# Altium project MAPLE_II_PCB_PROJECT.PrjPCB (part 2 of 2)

## Sheet MAPLE_II_HIGH_DENSITY_EXPANSION.SchDoc: High Density Expansion
size B; CompanyName: LeafLabs; DrawnBy: David McCoy; Engineer: David McCoy; Organization: LeafLabs; DocumentNumber: 6; Revision: A; SheetNumber: 6; SheetTotal: 6; ProjectPrettyName: Maple II
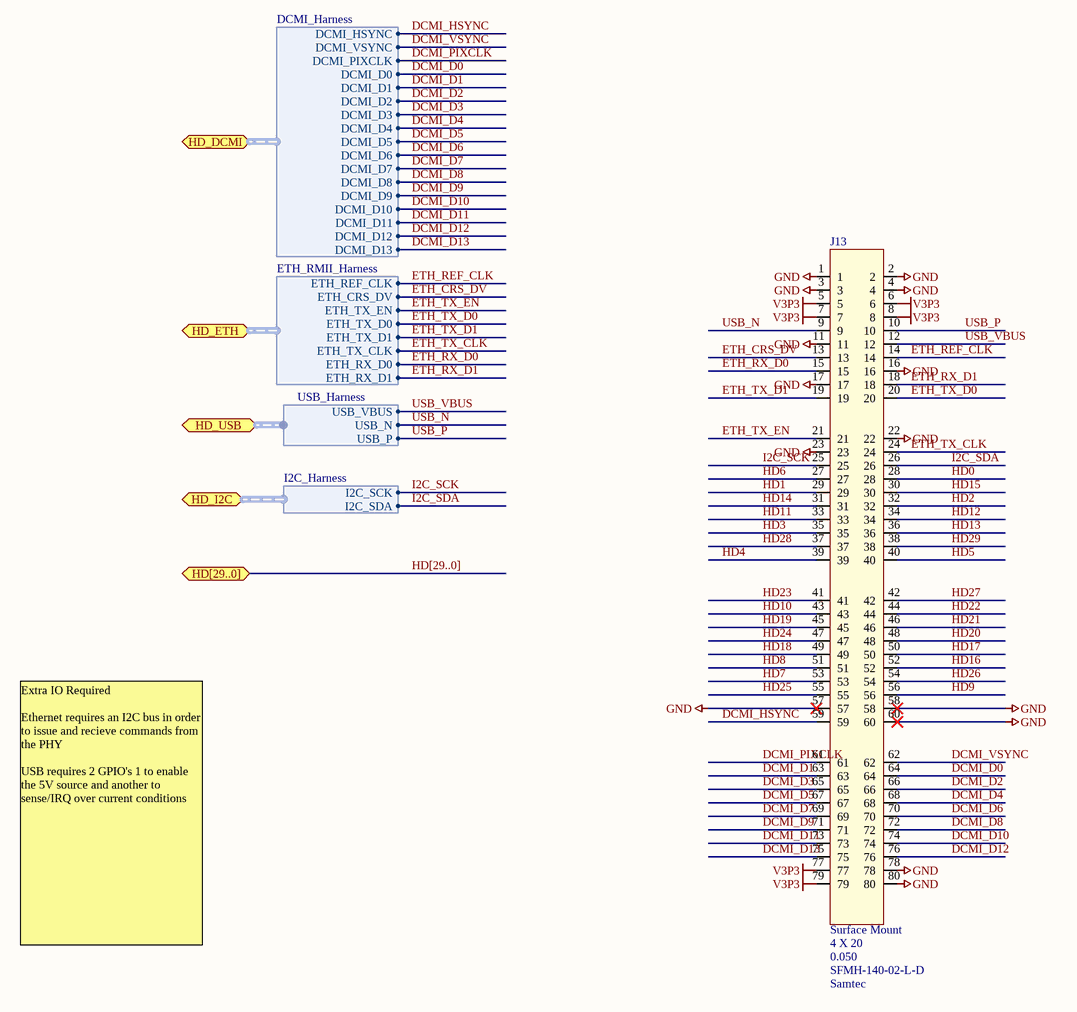
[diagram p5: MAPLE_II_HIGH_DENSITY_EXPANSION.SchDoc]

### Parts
J13  Mounting Type: Surface Mount  Number of Positions: 4 X 20  Pitch: 0.050  Manufacturer Part Number: SFMH-140-02-L-D  Manufacturer: Samtec  [SFMH-140]  (hidden comment: J_SFMH-140-02-L-D)

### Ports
HD[29..0], HD_DCMI (harness DCMI_Harness), HD_ETH (harness ETH_RMII_Harness), HD_I2C (harness I2C_Harness), HD_USB (harness USB_Harness)

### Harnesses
DCMI_Harness: DCMI_HSYNC, DCMI_VSYNC, DCMI_PIXCLK, DCMI_D0, DCMI_D1, DCMI_D2, DCMI_D3, DCMI_D4, DCMI_D5, DCMI_D6, DCMI_D7, DCMI_D8, DCMI_D9, DCMI_D10, DCMI_D11, DCMI_D12, DCMI_D13
ETH_RMII_Harness: ETH_REF_CLK, ETH_CRS_DV, ETH_TX_EN, ETH_TX_D0, ETH_TX_D1, ETH_TX_CLK, ETH_RX_D0, ETH_RX_D1
I2C_Harness: I2C_SCK, I2C_SDA
USB_Harness: USB_VBUS, USB_N, USB_P

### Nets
GND: J13.1 J13.2 J13.3 J13.4 J13.11 J13.16 J13.17 J13.22 J13.23 J13.57 J13.58 J13.60 J13.78 J13.80
V3P3: J13.5 J13.6 J13.7 J13.8 J13.77 J13.79
DCMI_D0: J13.64 ; port HD_DCMI.DCMI_D0
DCMI_D1: J13.63 ; port HD_DCMI.DCMI_D1
DCMI_D2: J13.66 ; port HD_DCMI.DCMI_D2
DCMI_D3: J13.65 ; port HD_DCMI.DCMI_D3
DCMI_D4: J13.68 ; port HD_DCMI.DCMI_D4
DCMI_D5: J13.67 ; port HD_DCMI.DCMI_D5
DCMI_D6: J13.70 ; port HD_DCMI.DCMI_D6
DCMI_D7: J13.69 ; port HD_DCMI.DCMI_D7
DCMI_D8: J13.72 ; port HD_DCMI.DCMI_D8
DCMI_D9: J13.71 ; port HD_DCMI.DCMI_D9
DCMI_D10: J13.74 ; port HD_DCMI.DCMI_D10
DCMI_D11: J13.73 ; port HD_DCMI.DCMI_D11
DCMI_D12: J13.76 ; port HD_DCMI.DCMI_D12
DCMI_D13: J13.75 ; port HD_DCMI.DCMI_D13
DCMI_HSYNC: J13.59 ; port HD_DCMI.DCMI_HSYNC
DCMI_PIXCLK: J13.61 ; port HD_DCMI.DCMI_PIXCLK  [project net D13]
DCMI_VSYNC: J13.62 ; port HD_DCMI.DCMI_VSYNC
ETH_CRS_DV: J13.13 ; port HD_ETH.ETH_CRS_DV  [project net D11]
ETH_REF_CLK: J13.14 ; port HD_ETH.ETH_REF_CLK  [project net D3]
ETH_RX_D0: J13.15 ; port HD_ETH.ETH_RX_D0
ETH_RX_D1: J13.18 ; port HD_ETH.ETH_RX_D1
ETH_TX_CLK: J13.24 ; port HD_ETH.ETH_TX_CLK
ETH_TX_D0: J13.20 ; port HD_ETH.ETH_TX_D0
ETH_TX_D1: J13.19 ; port HD_ETH.ETH_TX_D1
ETH_TX_EN: J13.21 ; port HD_ETH.ETH_TX_EN
HD0: J13.28
HD1: J13.29
HD2: J13.32
HD3: J13.35
HD4: J13.39
HD5: J13.40
HD6: J13.27
HD7: J13.53
HD8: J13.51
HD9: J13.56
HD10: J13.43
HD11: J13.33
HD12: J13.34
HD13: J13.36
HD14: J13.31
HD15: J13.30
HD16: J13.52
HD17: J13.50
HD18: J13.49
HD19: J13.45
HD20: J13.48
HD21: J13.46
HD22: J13.44
HD23: J13.41
HD24: J13.47
HD25: J13.55
HD26: J13.54
HD27: J13.42
HD28: J13.37
HD29: J13.38
I2C_SCK: J13.25 ; port HD_I2C.I2C_SCK  [project net D16]
I2C_SDA: J13.26 ; port HD_I2C.I2C_SDA  [project net D15]
USB_N: J13.9 ; port HD_USB.USB_N
USB_P: J13.10 ; port HD_USB.USB_P
USB_VBUS: J13.12 ; port HD_USB.USB_VBUS

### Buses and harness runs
bus HD[29..0] = port HD[29..0]

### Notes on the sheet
- Extra IO Required
  Ethernet requires an I2C bus in order to issue and recieve commands from the PHY
  USB requires 2 GPIO's 1 to enable the 5V source and another to sense/IRQ over current conditions

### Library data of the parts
J13 = J_SFMH-140-02-L-D: CONN RECEPT 4ROW X 20POS .50" SMT

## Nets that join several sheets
GND: MAPLE_II_PROCESSOR (76 pins), MAPLE_II_COMM_PROCESSOR (59 pins), MAPLE_II_POWER (19 pins), MAPLE_II_EXPANSION (7 pins), MAPLE_II_HIGH_DENSITY_EXPANSION (14 pins)
V3P3: MAPLE_II_PROCESSOR (41 pins), MAPLE_II_COMM_PROCESSOR (19 pins), MAPLE_II_POWER (6 pins), MAPLE_II_EXPANSION (J2.5 R1.1 R3.1), MAPLE_II_HIGH_DENSITY_EXPANSION (6 pins)
V5P0: MAPLE_II_POWER (C2.2 J7.2 U1.21), MAPLE_II_EXPANSION (J2.7)
V_USB_5P0: MAPLE_II_COMM_PROCESSOR (J1.1), MAPLE_II_POWER (J7.3)
VA3P3: MAPLE_II_PROCESSOR (C29.2 C30.2 L3.1 U2.R1), MAPLE_II_EXPANSION (J2.4)
VIN: MAPLE_II_POWER (J6.2 J7.1), MAPLE_II_EXPANSION (J2.1)
A0: MAPLE_II_PROCESSOR (U2.E2), MAPLE_II_EXPANSION (J4.1)
A1: MAPLE_II_PROCESSOR (U2.H3), MAPLE_II_EXPANSION (J4.2)
A2: MAPLE_II_PROCESSOR (U2.H2), MAPLE_II_EXPANSION (J4.3)
A3: MAPLE_II_PROCESSOR (U2.J2), MAPLE_II_EXPANSION (J4.4)
A4: MAPLE_II_PROCESSOR (U2.J3), MAPLE_II_EXPANSION (J4.5)
A5: MAPLE_II_PROCESSOR (U2.K3), MAPLE_II_EXPANSION (J4.6)
BOOT0: MAPLE_II_PROCESSOR (U2.D6 U2.D10), MAPLE_II_COMM_PROCESSOR (U3.35), MAPLE_II_EXPANSION (C1.2 R1.2 S1.1)
BOOT1: MAPLE_II_PROCESSOR (J10.1 R19.1 U2.M6), MAPLE_II_COMM_PROCESSOR (U3.14)
COMM_UART1_RX: MAPLE_II_PROCESSOR (U2.R12), MAPLE_II_COMM_PROCESSOR (U3.26)
COMM_UART1_TX: MAPLE_II_PROCESSOR (U2.R13), MAPLE_II_COMM_PROCESSOR (U3.25)
D0: MAPLE_II_PROCESSOR (U2.R2), MAPLE_II_EXPANSION (J5.1)
D1: MAPLE_II_PROCESSOR (U2.P2), MAPLE_II_EXPANSION (J5.2)
D2: MAPLE_II_PROCESSOR (U2.N3), MAPLE_II_EXPANSION (J5.3)
D3: MAPLE_II_PROCESSOR (U2.N2), MAPLE_II_EXPANSION (J5.4), MAPLE_II_HIGH_DENSITY_EXPANSION (J13.14)
D4: MAPLE_II_PROCESSOR (R34#1.2 U2.A6), MAPLE_II_EXPANSION (J5.5)
D5: MAPLE_II_PROCESSOR (U2.B6), MAPLE_II_EXPANSION (J5.6)
D6: MAPLE_II_PROCESSOR (U2.F15), MAPLE_II_EXPANSION (J5.7)
D7: MAPLE_II_PROCESSOR (U2.E15), MAPLE_II_EXPANSION (J5.8)
D8: MAPLE_II_PROCESSOR (R15.2 U2.D15), MAPLE_II_EXPANSION (J3.1)
D9: MAPLE_II_PROCESSOR (U2.B5), MAPLE_II_EXPANSION (J3.2)
D10: MAPLE_II_PROCESSOR (U2.N4), MAPLE_II_EXPANSION (J3.3)
D11: MAPLE_II_PROCESSOR (U2.R3), MAPLE_II_EXPANSION (J3.4), MAPLE_II_HIGH_DENSITY_EXPANSION (J13.13)
D12: MAPLE_II_PROCESSOR (U2.P3), MAPLE_II_EXPANSION (J3.5)
D13: MAPLE_II_PROCESSOR (U2.P4), MAPLE_II_EXPANSION (J3.6 LED1.2), MAPLE_II_HIGH_DENSITY_EXPANSION (J13.61)
D14: MAPLE_II_PROCESSOR (U2.F14), MAPLE_II_EXPANSION (J3.8)
D15: MAPLE_II_PROCESSOR (U2.J4), MAPLE_II_EXPANSION (J3.9), MAPLE_II_HIGH_DENSITY_EXPANSION (J13.26)
D16: MAPLE_II_PROCESSOR (U2.H4), MAPLE_II_EXPANSION (J3.10), MAPLE_II_HIGH_DENSITY_EXPANSION (J13.25)
DCMI_D0: MAPLE_II_PROCESSOR (U2.H15), MAPLE_II_HIGH_DENSITY_EXPANSION (J13.64)
DCMI_D1: MAPLE_II_PROCESSOR (U2.G15), MAPLE_II_HIGH_DENSITY_EXPANSION (J13.63)
DCMI_D2: MAPLE_II_PROCESSOR (U2.G14), MAPLE_II_HIGH_DENSITY_EXPANSION (J13.66)
DCMI_D3: MAPLE_II_PROCESSOR (U2.A3), MAPLE_II_HIGH_DENSITY_EXPANSION (J13.65)
DCMI_D4: MAPLE_II_PROCESSOR (R35#1.2 U2.B13), MAPLE_II_HIGH_DENSITY_EXPANSION (J13.68)
DCMI_D5: MAPLE_II_PROCESSOR (U2.D4), MAPLE_II_HIGH_DENSITY_EXPANSION (J13.67)
DCMI_D6: MAPLE_II_PROCESSOR (U2.A5), MAPLE_II_HIGH_DENSITY_EXPANSION (J13.70)
DCMI_D7: MAPLE_II_PROCESSOR (U2.B4), MAPLE_II_HIGH_DENSITY_EXPANSION (J13.69)
DCMI_D8: MAPLE_II_PROCESSOR (U2.B14), MAPLE_II_HIGH_DENSITY_EXPANSION (J13.72)
DCMI_D9: MAPLE_II_PROCESSOR (U2.A12), MAPLE_II_HIGH_DENSITY_EXPANSION (J13.71)
DCMI_D10: MAPLE_II_PROCESSOR (U2.C13), MAPLE_II_HIGH_DENSITY_EXPANSION (J13.74)
DCMI_D11: MAPLE_II_PROCESSOR (U2.D12), MAPLE_II_HIGH_DENSITY_EXPANSION (J13.73)
DCMI_D12: MAPLE_II_PROCESSOR (U2.P6), MAPLE_II_HIGH_DENSITY_EXPANSION (J13.76)
DCMI_D13: MAPLE_II_PROCESSOR (U2.B7), MAPLE_II_HIGH_DENSITY_EXPANSION (J13.75)
DCMI_HSYNC: MAPLE_II_PROCESSOR (U2.M12), MAPLE_II_HIGH_DENSITY_EXPANSION (J13.59)
DCMI_VSYNC: MAPLE_II_PROCESSOR (U2.C4), MAPLE_II_HIGH_DENSITY_EXPANSION (J13.62)
ETH_RX_D0: MAPLE_II_PROCESSOR (U2.N5), MAPLE_II_HIGH_DENSITY_EXPANSION (J13.15)
ETH_RX_D1: MAPLE_II_PROCESSOR (U2.P5), MAPLE_II_HIGH_DENSITY_EXPANSION (J13.18)
ETH_TX_CLK: MAPLE_II_PROCESSOR (U2.D1), MAPLE_II_HIGH_DENSITY_EXPANSION (J13.24)
ETH_TX_D0: MAPLE_II_PROCESSOR (U2.A8), MAPLE_II_HIGH_DENSITY_EXPANSION (J13.20)
ETH_TX_D1: MAPLE_II_PROCESSOR (U2.A7), MAPLE_II_HIGH_DENSITY_EXPANSION (J13.19)
ETH_TX_EN: MAPLE_II_PROCESSOR (U2.B9), MAPLE_II_HIGH_DENSITY_EXPANSION (J13.21)
HD0: MAPLE_II_PROCESSOR (U2.M2), MAPLE_II_HIGH_DENSITY_EXPANSION (J13.28)
HD1: MAPLE_II_PROCESSOR (U2.M3), MAPLE_II_HIGH_DENSITY_EXPANSION (J13.29)
HD2: MAPLE_II_PROCESSOR (U2.M4), MAPLE_II_HIGH_DENSITY_EXPANSION (J13.32)
HD3: MAPLE_II_PROCESSOR (U2.M5), MAPLE_II_HIGH_DENSITY_EXPANSION (J13.35)
HD4: MAPLE_II_PROCESSOR (U2.E1), MAPLE_II_HIGH_DENSITY_EXPANSION (J13.39)
HD5: MAPLE_II_PROCESSOR (U2.F1), MAPLE_II_HIGH_DENSITY_EXPANSION (J13.40)
HD6: MAPLE_II_PROCESSOR (U2.P12), MAPLE_II_HIGH_DENSITY_EXPANSION (J13.27)
HD7: MAPLE_II_PROCESSOR (R28.2 U2.C15), MAPLE_II_HIGH_DENSITY_EXPANSION (J13.53)
HD8: MAPLE_II_PROCESSOR (R31#1.2 U2.B15), MAPLE_II_HIGH_DENSITY_EXPANSION (J13.51)
HD9: MAPLE_II_PROCESSOR (U2.B12), MAPLE_II_HIGH_DENSITY_EXPANSION (J13.56)
HD10: MAPLE_II_PROCESSOR (U2.C12), MAPLE_II_HIGH_DENSITY_EXPANSION (J13.43)
HD11: MAPLE_II_PROCESSOR (U2.P10), MAPLE_II_HIGH_DENSITY_EXPANSION (J13.33)
HD12: MAPLE_II_PROCESSOR (U2.R10), MAPLE_II_HIGH_DENSITY_EXPANSION (J13.34)
HD13: MAPLE_II_PROCESSOR (U2.N11), MAPLE_II_HIGH_DENSITY_EXPANSION (J13.36)
HD14: MAPLE_II_PROCESSOR (U2.P11), MAPLE_II_HIGH_DENSITY_EXPANSION (J13.31)
HD15: MAPLE_II_PROCESSOR (U2.R11), MAPLE_II_HIGH_DENSITY_EXPANSION (J13.30)
HD16: MAPLE_II_PROCESSOR (U2.L13), MAPLE_II_HIGH_DENSITY_EXPANSION (J13.52)
HD17: MAPLE_II_PROCESSOR (U2.L12), MAPLE_II_HIGH_DENSITY_EXPANSION (J13.50)
HD18: MAPLE_II_PROCESSOR (U2.K12), MAPLE_II_HIGH_DENSITY_EXPANSION (J13.49)
HD19: MAPLE_II_PROCESSOR (U2.E12), MAPLE_II_HIGH_DENSITY_EXPANSION (J13.45)
HD20: MAPLE_II_PROCESSOR (U2.E13), MAPLE_II_HIGH_DENSITY_EXPANSION (J13.48)
HD21: MAPLE_II_PROCESSOR (U2.D13), MAPLE_II_HIGH_DENSITY_EXPANSION (J13.46)
HD22: MAPLE_II_PROCESSOR (U2.C3), MAPLE_II_HIGH_DENSITY_EXPANSION (J13.44)
HD23: MAPLE_II_PROCESSOR (U2.C2), MAPLE_II_HIGH_DENSITY_EXPANSION (J13.41)
HD24: MAPLE_II_PROCESSOR (U2.E14), MAPLE_II_HIGH_DENSITY_EXPANSION (J13.47)
HD25: MAPLE_II_PROCESSOR (U2.D14), MAPLE_II_HIGH_DENSITY_EXPANSION (J13.55)
HD26: MAPLE_II_PROCESSOR (U2.C14), MAPLE_II_HIGH_DENSITY_EXPANSION (J13.54)
HD27: MAPLE_II_PROCESSOR (U2.D3), MAPLE_II_HIGH_DENSITY_EXPANSION (J13.42)
HD28: MAPLE_II_PROCESSOR (U2.E3), MAPLE_II_HIGH_DENSITY_EXPANSION (J13.37)
HD29: MAPLE_II_PROCESSOR (U2.E4), MAPLE_II_HIGH_DENSITY_EXPANSION (J13.38)
~{MCU_RST}: MAPLE_II_PROCESSOR (R22.1 S2.1 U2.J1), MAPLE_II_EXPANSION (J2.6)
NetR22_2: MAPLE_II_PROCESSOR (R22.2), MAPLE_II_COMM_PROCESSOR (U3.36)
USB_N: MAPLE_II_PROCESSOR (U2.R14), MAPLE_II_HIGH_DENSITY_EXPANSION (J13.9)
USB_P: MAPLE_II_PROCESSOR (U2.R15), MAPLE_II_HIGH_DENSITY_EXPANSION (J13.10)
USB_VBUS: MAPLE_II_PROCESSOR (U2.P13), MAPLE_II_HIGH_DENSITY_EXPANSION (J13.12)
